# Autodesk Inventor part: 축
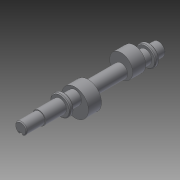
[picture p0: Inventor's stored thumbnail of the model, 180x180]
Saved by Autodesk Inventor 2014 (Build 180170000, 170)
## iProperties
Created: 2014-12
Part Number: 축
Material: 일반
Document SubType Name: Modeling
Designer: Owner
Density: 1 g/cm^3
Appearance: 기본값
Author: Owner
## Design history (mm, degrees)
sketch "스케치2"
  geometry: L1 (-90, 0)-(90, 0); L2 (-90, 0)-(-90, 7.5); L3 (-90, 7.5)-(-66, 7.5); L4 (-66, 7.5)-(-66, 8.5); L5 (-66, 8.5)-(-39, 8.5); L6 (-39, 8.5)-(-39, 13); L7 (-39, 13)-(-34, 13); L8 (-34, 13)-(-34, 8.5); L9 (-34, 8.5)-(72, 8.5); L10 (72, 8.5)-(72, 13); L11 (72, 13)-(77, 13); L12 (77, 13)-(77, 8.5); L13 (77, 8.5)-(90, 8.5); L14 (90, 8.5)-(90, 0); 3 further points
  constraints: 28 end point, 6 parallel, 6 perpendicular, 2 midpoint, 1 coincident, 1 collinear, 1 horizontal, 1 horizontal alignment
  dimensions: "d0" = 180 distance of L1.start L1.end; "d1" = 15 diameter of L3 L1; "d2" = 17 diameter of L5 L1; "d3" = 24 distance of L2.end L3.end; "d4" = 27 distance of L4.end L5.end; "d5" = 26 diameter of L7 L1; "d6" = 5 distance of L6.end L7.end; "d7" = 17 diameter of L13 L1; "d8" = 26 diameter of L11 L1; "d9" = 5 distance of L10.end L11.end; "d10" = 13 distance of L12.end L13.end
revolve "회전1" sketch "스케치2" stored, may be unused: angle "d11" = 90 deg
node "작업 평면1"
sketch "스케치3"
  geometry: C1 r 17.5 at (0, 6); 1 further point
  constraints: 1 centre point, 1 vertical alignment
  dimensions: "d13" = 6 distance of point (0, 0) C1.centre; "d14" = 35 diameter of C1
extrude "돌출1" join sketch "스케치3" distance "d15" = 17; taper "d16" = 0 deg
node "작업 평면2"
sketch "스케치4"
  geometry: C1 r 15 at (0, -11); 1 further point
  constraints: 1 centre point, 1 vertical alignment
  dimensions: "d18" = 5 distance of C1.centre point (0, -6); "d19" = 30 diameter of C1
extrude "돌출2" join sketch "스케치4" distance "d20" = 17; taper "d21" = 0 deg
node "작업 평면3"
sketch "스케치5"
  geometry: L1 (7.5, -12)-(-7.5, -12) reference; L2 (-2.5, -12)-(-2.5, 5.5); L3 (2.5, -12)-(2.5, 5.5); A1 r 2.5 centre (0, 5.5) between (2.5, 5.5) and (-2.5, 5.5); 2 further points
  constraints: 4 end point, 2 point on circle, 2 point on line, 2 tangent, 1 centre point, 1 midpoint, 1 parallel, 1 perpendicular, 1 vertical alignment
  dimensions: "d22" = 5 distance between parallel lines of L3 L2; "d23" = 20 dimension on A1 L1
extrude "돌출3" cut sketch "스케치5" distance "d24" = 3; taper "d25" = 0 deg
chamfer "모따기1" distance "d26" = 1; stored, may be unused: second distance "d27" = 2, angle "d28" = 45 deg
chamfer "모따기2" distance "d29" = 1; stored, may be unused: second distance "d30" = 2, angle "d31" = 45 deg
node "솔리드1"
other parameters: "d12" = 14.5, "d17" = 43
